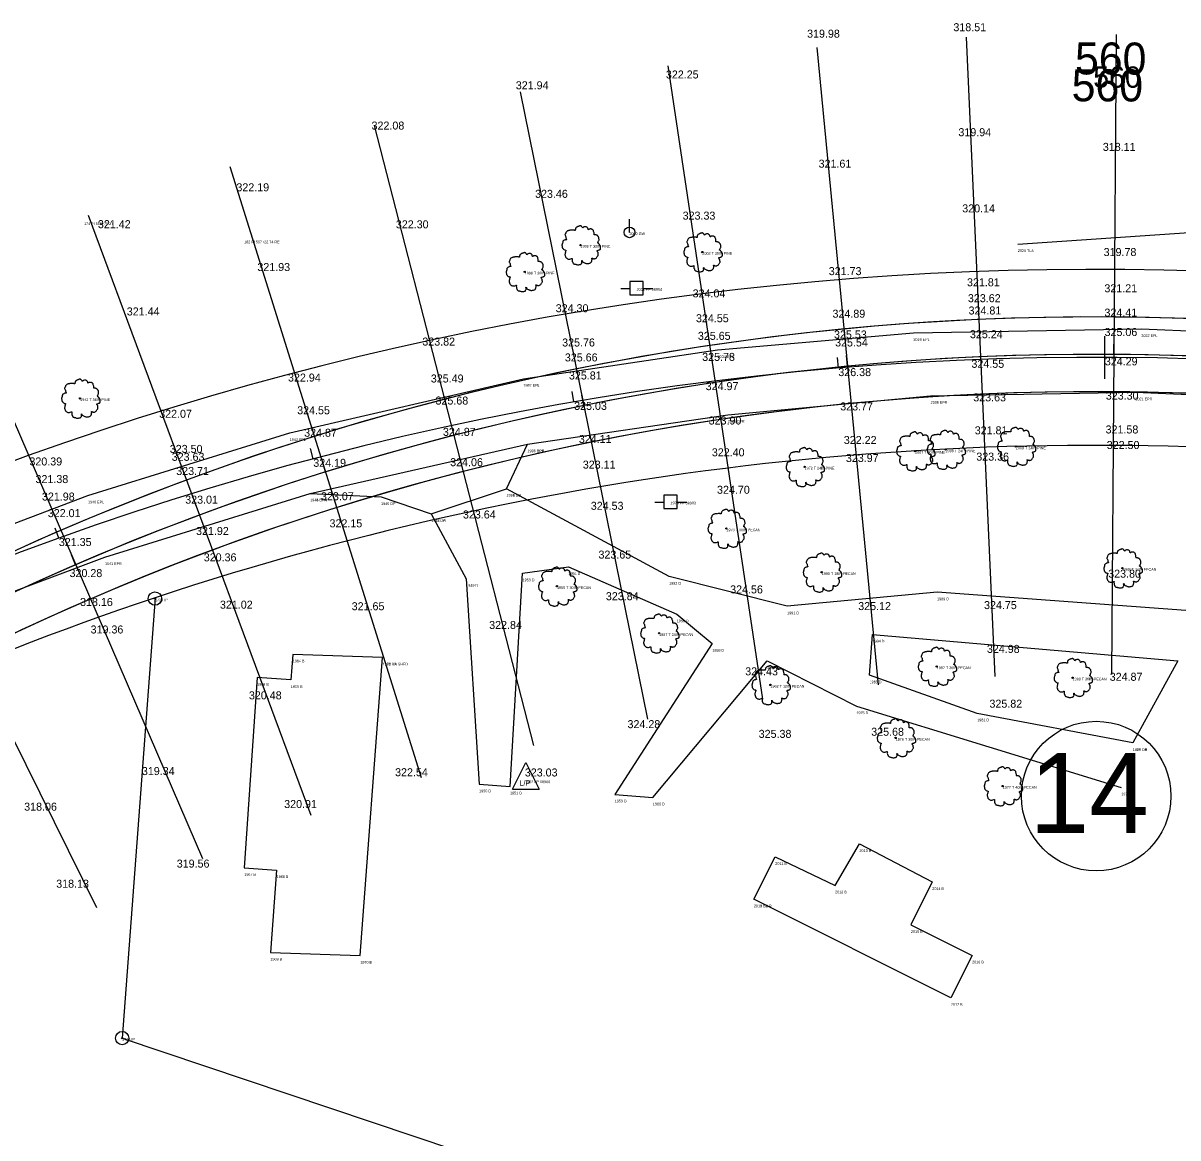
# Model space of a CAD drawing. Extents: x 49683 to 58852, y 49525 to 54803.
# Drawn here: x 56390.1 to 56823.1, y 53778.4 to 54196.4 of the extents above; entities that cross this region are included whole.
import ezdxf

# ---------------------------------------------------------------- set-up
doc = ezdxf.new("R2010")
doc.units = 0
for name, color, linetype in [('Level 1', 7, 'Continuous'), ('Level 11', 7, 'Continuous'), ('Level 12', 7, 'Continuous'), ('Level 13', 7, 'Continuous'), ('Level 19', 7, 'Continuous'), ('Level 20', 7, 'Continuous'), ('Level 21', 7, 'Continuous'), ('Level 25', 7, 'Continuous'), ('Level 29', 7, 'Continuous'), ('Level 3', 7, 'Continuous'), ('Level 32', 7, 'Continuous'), ('Level 50', 7, 'Continuous'), ('Level 51', 7, 'Continuous'), ('Level 53', 7, 'Continuous'), ('Level 58', 7, 'Continuous'), ('Level 59', 7, 'Continuous'), ('Level 61', 7, 'Continuous'), ('Level 62', 7, 'Continuous'), ('Level 63', 7, 'Continuous'), ('Level 8', 7, 'Continuous'), ('Level 9', 7, 'Continuous')]:
    doc.layers.add(name, color=color, linetype=linetype)

# ---------------------------------------------------------------- blocks, each defined once
blk = doc.blocks.new('IP')
at = {"layer": 'Level 12'}
for radius in [2.5, 0.25]:
    blk.add_circle((0, 0), radius, dxfattribs=at)
blk = doc.blocks.new('T1')
at = {"layer": 'Level 11'}
for centre, radius in [((0, 0), 0.25), ((-0.01, -0.02), 0.0001)]:
    blk.add_circle(centre, radius, dxfattribs=at)
for points in [[(0.13, 7.17), (-0.17, 7.19), (-0.49, 7.09), (-0.74, 6.99), (-0.97, 6.92), (-1.19, 6.82), (-1.49, 6.64), (-1.72, 6.44), (-1.84, 6.19), (-1.89, 5.97), (-1.94, 5.69), (-1.94, 5.52), (-2.07, 5.49), (-2.22, 5.52), (-2.47, 5.59), (-2.72, 5.59), (-2.97, 5.59), (-3.32, 5.57), (-3.67, 5.57), (-3.94, 5.52), (-4.27, 5.47), (-4.64, 5.34), (-4.99, 5.22), (-5.29, 4.97), (-5.54, 4.49), (-5.67, 4.14), (-5.82, 3.89), (-5.67, 3.44), (-5.49, 3.09), (-5.47, 2.89), (-5.39, 2.47), (-5.29, 2.24), (-5.17, 2.04), (-5.24, 2.02), (-5.62, 1.97), (-5.92, 1.87), (-6.34, 1.64), (-6.57, 1.42), (-6.67, 1.09), (-6.69, 0.75), (-6.79, 0.55), (-6.87, 0.27), (-6.89, 0.2), (-6.94, -0.13), (-6.84, -0.58), (-6.82, -0.93), (-6.69, -1.15), (-6.54, -1.33), (-6.37, -1.58), (-5.97, -1.8), (-5.64, -1.9), (-5.44, -1.93), (-5.62, -2.43), (-5.67, -2.78), (-5.79, -3.18), (-5.79, -3.25), (-5.84, -3.73), (-5.69, -4.05), (-5.62, -4.43), (-5.44, -4.65), (-5.17, -4.95), (-4.84, -5.18), (-4.34, -5.3), (-3.94, -5.28), (-3.37, -5.1), (-3.12, -5.03), (-3.14, -5.2), (-3.12, -5.58), (-3.12, -6), (-2.97, -6.33), (-2.87, -6.6), (-2.72, -6.85), (-2.39, -7.08), (-1.99, -7.15), (-1.57, -7.3), (-1.12, -7.38), (-0.62, -7.4), (-0.02, -7.25), (0.26, -7.13), (0.36, -6.95), (0.56, -6.58), (0.51, -6.35), (0.53, -5.75), (0.63, -5.93), (0.81, -6.28), (1.31, -6.58), (1.71, -6.75), (2.18, -6.9), (2.48, -6.98), (2.96, -6.9), (3.33, -6.83), (3.71, -6.7), (4.01, -6.43), (4.18, -6.15), (4.23, -5.88), (4.31, -5.5), (4.36, -5.33)], [(4.36, -5.33), (4.28, -5.15), (4.23, -4.9), (4.31, -4.93), (4.48, -4.98), (4.75, -5.1), (4.98, -5.18), (5.3, -5.15), (5.58, -5.05), (6.03, -4.78), (6.3, -4.3), (6.58, -3.9), (6.65, -3.58), (6.6, -3.35), (6.58, -2.85), (6.38, -2.6), (6.33, -2.48), (6.23, -2.08), (6.3, -2.03), (6.58, -1.98), (6.95, -1.85), (7.23, -1.73), (7.45, -1.55), (7.53, -1.33), (7.5, -0.93), (7.55, -0.53), (7.48, -0.38), (7.38, -0.23), (7.3, -0.03), (7.15, 0.12), (7.05, 0.27), (6.95, 0.37), (6.83, 0.52), (6.65, 0.65), (6.5, 0.7), (6.45, 0.85), (6.6, 1.04), (6.65, 1.14), (6.68, 1.37), (6.9, 1.72), (6.95, 2.12), (6.9, 2.54), (6.85, 2.82), (6.7, 3.09), (6.5, 3.34), (6.38, 3.52), (6.2, 3.64), (5.88, 3.77), (5.63, 3.82), (5.28, 3.82), (5.08, 3.87), (5.1, 3.92), (5.1, 4.07), (5.1, 4.34), (5.03, 4.79), (4.88, 5.29), (4.88, 5.32), (4.78, 5.57), (4.56, 5.77), (4.38, 5.87), (4.18, 5.99), (3.93, 6.02), (3.63, 6.02), (3.36, 5.97), (3.16, 5.87), (2.98, 5.74), (2.91, 5.89), (2.81, 6.19), (2.76, 6.34), (2.61, 6.52), (2.38, 6.72), (1.93, 6.84), (1.31, 6.77), (1.01, 6.57), (0.86, 6.39), (0.81, 6.52), (0.61, 6.72), (0.51, 6.89), (0.33, 7.02), (0.18, 7.12), (0.08, 7.17)]]:
    blk.add_spline(points, degree=3, dxfattribs=at)
blk = doc.blocks.new('LP')
at = {"layer": 'Level 9'}
for p, q in [((-4.79, -3.23), (0.21, 6.77)), ((0.21, 6.77), (5.21, -3.23)), ((-4.79, -3.23), (5.21, -3.23))]:
    blk.add_line(p, q, dxfattribs=at)
blk.add_text('L/P', height=2, dxfattribs=at).set_placement((-2.19, -1.95))
blk = doc.blocks.new('PP')
at = {"layer": 'Level 9'}
for p, q in [((2.53, 2.45), (-2.47, 2.45)), ((-2.47, 2.45), (-2.47, -2.55)), ((2.53, -2.55), (2.53, 2.45)), ((-5.91, -0.11), (-2.44, -0.11)), ((-2.47, -2.55), (2.53, -2.55)), ((2.45, -0.11), (6.09, -0.11))]:
    blk.add_line(p, q, dxfattribs=at)
blk = doc.blocks.new('GW')
at = {"layer": 'Level 9'}
blk.add_line((0, 0), (0, 5), dxfattribs=at)
blk.add_circle((0, 0), 2, dxfattribs=at)

msp = doc.modelspace()

# ---------------------------------------------------------------- linework, layer by layer
at = {"layer": 'Level 1'}
for p, q in [((56795.65, 54071.04), (56795.68, 54079.04)), ((56695.76, 54067.02), (56695.43, 54071.01)), ((56795.62, 54063.04), (56795.65, 54071.04)), ((56596.61, 54054.31), (56595.92, 54058.26)), ((56498.93, 54033.01), (56497.91, 54036.88)), ((56403.49, 54003.28), (56402.13, 54007.04))]:
    msp.add_line(p, q, dxfattribs=at)
at = {"layer": 'Level 11'}
msp.add_line((56763.02, 54113.51), (56919.7, 54124.18), dxfattribs=at)
at = {"layer": 'Level 12'}
for p, q in [((56439.6, 53980.87), (56427.28, 53815.81)), ((56427.28, 53815.81), (56690.99, 53727.29))]:
    msp.add_line(p, q, dxfattribs=at)
at = {"layer": 'Level 13'}
for radius, start, end in [(1178.92, 86.60044, 131.63335), (1112.92, 83.49442, 108.44495), (1112.92, 108.44495, 131.63335)]:
    msp.add_arc((56791.72, 52925.13), radius, start, end, dxfattribs=at)
at = {"layer": 'Level 19'}
for p, q in [((56799.06, 54072.17), (56799.12, 54080.17)), ((56699.21, 54067.73), (56698.82, 54071.71)), ((56799.06, 54072.17), (56799, 54064.17)), ((56600.34, 54052.98), (56599.55, 54056.9)), ((56503.54, 54028.08), (56502.34, 54031.9)), ((56409.83, 53993.31), (56408.24, 53996.98))]:
    msp.add_line(p, q, dxfattribs=at)
msp.add_arc((56791.96, 53107.19), 965, 83.49443, 131.63337, dxfattribs=at)
at = {"layer": 'Level 20'}
for radius, start in [(979, 83.49447), (951, 83.49446)]:
    msp.add_arc((56791.96, 53107.19), radius, start, 131.63337, dxfattribs=at)
at = {"layer": 'Level 25'}
msp.add_circle((56792.42, 53906.55), 28.04, dxfattribs=at)
at = {"layer": 'Level 29'}
for p, q in [((56795.65, 54071.04), (56795.68, 54079.04)), ((56695.76, 54067.02), (56695.43, 54071.01)), ((56596.61, 54054.31), (56595.93, 54058.26)), ((56498.93, 54033.01), (56497.91, 54036.88)), ((56403.49, 54003.28), (56402.14, 54007.04))]:
    msp.add_line(p, q, dxfattribs=at)
msp.add_arc((56791.72, 52925.13), 1145.92, 83.49443, 131.63333, dxfattribs=at)
at = {"layer": 'Level 3'}
for p, q in [((56723.9, 54080.24), (56809.36, 54081.7)), ((56809.36, 54081.7), (56872.82, 54079.01)), ((56650.48, 54073.81), (56723.9, 54080.24)), ((56577.69, 54063.01), (56650.48, 54073.81)), ((56490.09, 54042.73), (56577.69, 54063.01)), ((56654.29, 54049.54), (56730.36, 54056.66)), ((56730.36, 54056.66), (56807.13, 54057.96)), ((56807.13, 54057.96), (56873.04, 54055.26)), ((56579.24, 54038.47), (56654.29, 54049.54)), ((56414.45, 54019.29), (56490.09, 54042.73)), ((56497.78, 54020.06), (56579.24, 54038.47)), ((56340.54, 53991.29), (56414.45, 54019.29)), ((56420.81, 53996.17), (56497.78, 54020.06)), ((56350.09, 53969.49), (56420.81, 53996.17))]:
    msp.add_line(p, q, dxfattribs=at)
at = {"layer": 'Level 50'}
for p, q in [((56743.74, 54191.12), (56754.41, 53951.36)), ((56799.95, 54192.16), (56798.18, 53952.17)), ((56687.67, 54187.17), (56710.74, 53948.28)), ((56631.88, 54180.32), (56667.29, 53942.95)), ((56576.52, 54170.59), (56624.17, 53935.37)), ((56521.73, 54158), (56581.51, 53925.57)), ((56467.67, 54142.6), (56539.4, 53913.57)), ((56414.48, 54124.41), (56497.98, 53899.41)), ((56362.31, 54103.5), (56457.35, 53883.12)), ((56311.29, 54079.91), (56417.61, 53864.75))]:
    msp.add_line(p, q, dxfattribs=at)
at = {"layer": 'Level 63'}
for radius in [979, 965, 965, 951]:
    msp.add_arc((56791.96, 53107.19), radius, 87.29416, 127.83345, dxfattribs=at)
at = {"layer": 'Level 8'}
for p, q in [((56571.37, 54021.8), (56579.24, 54038.47)), ((56543.14, 54012.37), (56571.37, 54021.8)), ((56632.32, 53988.82), (56571.37, 54021.8)), ((56497.78, 54020.06), (56524.35, 54018.72)), ((56524.35, 54018.72), (56543.14, 54012.37)), ((56543.14, 54012.37), (56556.26, 53988.01)), ((56577.39, 53990.09), (56594.57, 53992.46)), ((56594.57, 53992.46), (56635.17, 53974.75)), ((56556.26, 53988.01), (56561.1, 53910.97)), ((56572.68, 53910.19), (56577.39, 53990.09)), ((56676.58, 53977.7), (56632.32, 53988.82)), ((56732.77, 53982.97), (56676.58, 53977.7)), ((56836.65, 53975.32), (56732.77, 53982.97)), ((56635.17, 53974.75), (56648.5, 53963.72)), ((56707.47, 53951.83), (56708.57, 53967.14)), ((56708.57, 53967.14), (56823.01, 53957.2)), ((56648.5, 53963.72), (56611.93, 53907.19)), ((56491.23, 53959.69), (56490.52, 53950.11)), ((56524.93, 53958.52), (56491.23, 53959.69)), ((56516.55, 53846.72), (56524.93, 53958.52)), ((56626.22, 53906.07), (56669.07, 53957.29)), ((56669.07, 53957.29), (56702.53, 53940.27)), ((56823.01, 53957.2), (56806.15, 53926.5)), ((56747.83, 53937.57), (56707.47, 53951.83)), ((56477.85, 53950.96), (56473.05, 53879.64)), ((56490.52, 53950.11), (56477.85, 53950.96)), ((56702.53, 53940.27), (56801.83, 53909.79)), ((56806.15, 53926.5), (56747.83, 53937.57)), ((56561.1, 53910.97), (56572.68, 53910.19)), ((56611.93, 53907.19), (56626.22, 53906.07)), ((56694.51, 53873.08), (56703.69, 53888.59)), ((56703.69, 53888.59), (56730.98, 53874.36)), ((56664.09, 53867.85), (56672.11, 53883.72)), ((56672.11, 53883.72), (56694.51, 53873.08)), ((56473.05, 53879.64), (56485.18, 53878.82)), ((56485.18, 53878.82), (56482.86, 53847.89)), ((56730.98, 53874.36), (56722.98, 53858.23)), ((56737.97, 53830.92), (56664.09, 53867.85)), ((56722.98, 53858.23), (56745.89, 53846.83)), ((56482.86, 53847.89), (56516.55, 53846.72)), ((56745.89, 53846.83), (56737.97, 53830.92))]:
    msp.add_line(p, q, dxfattribs=at)

# ---------------------------------------------------------------- block references
at = {"layer": 'Level 11'}
for p in [(56599.09, 54113.16), (56644.76, 54110.52), (56578.18, 54103.12), (56411.51, 54055.66), (56724.52, 54035.91), (56735.97, 54036.49), (56762.31, 54037.59), (56683.1, 54030), (56653.82, 54006.87), (56802.24, 53992.01), (56689.55, 53990.45), (56590.28, 53985.2), (56628.59, 53967.6), (56732.63, 53955.14), (56783.57, 53950.92), (56670.3, 53948.23), (56717.25, 53928.33), (56757.4, 53910.32)]:
    msp.add_blockref('T1', p, dxfattribs=at)
at = {"layer": 'Level 12'}
for p in [(56439.58, 53980.62), (56427.28, 53815.81)]:
    msp.add_blockref('IP', p, dxfattribs=at)
at = {"layer": 'Level 9'}
for name, p in [('GW', (56617.45, 54117.92)), ('PP', (56620.12, 54097.01)), ('PP', (56632.83, 54016.9)), ('LP', (56578.36, 53912.4))]:
    msp.add_blockref(name, p, dxfattribs=at)

# ---------------------------------------------------------------- texts
at = {"layer": 'Level 19'}
msp.add_text('560', height=8, rotation=359.5783, dxfattribs=at).set_placement((56791.28, 54172.23))
at = {"layer": 'Level 21'}
for rotation, p in [(359.8036, (56784.46, 54177.15)), (359.8035, (56783.21, 54167.08))]:
    msp.add_text('560', height=12, rotation=rotation, dxfattribs=at).set_placement(p)
at = {"layer": 'Level 25'}
msp.add_text('14', height=30, dxfattribs=at).set_placement((56767.49, 53892.67))
at = {"layer": 'Level 32'}
for s, p in [('319.98', (56684.05, 54190.91)), ('318.51', (56738.89, 54193.33)), ('322.25', (56631.11, 54175.61)), ('321.94', (56574.84, 54171.56)), ('322.08', (56520.77, 54156.45)), ('319.94', (56740.77, 54153.97)), ('318.11', (56794.92, 54148.46)), ('321.61', (56688.36, 54142.16)), ('322.19', (56470.1, 54133.32)), ('323.46', (56582.07, 54130.86)), ('323.33', (56637.39, 54122.69)), ('320.14', (56742.21, 54125.4)), ('321.42', (56418.18, 54119.48)), ('322.30', (56529.88, 54119.42)), ('319.78', (56795.22, 54109.03)), ('321.93', (56477.96, 54103.41)), ('321.73', (56692.17, 54101.88)), ('321.81', (56743.99, 54097.7)), ('321.21', (56795.5, 54095.44)), ('324.04', (56641.14, 54093.53)), ('323.62', (56744.33, 54091.73)), ('321.44', (56429, 54086.76)), ('324.30', (56589.81, 54087.97)), ('324.81', (56744.58, 54087.12)), ('324.55', (56642.39, 54084.22)), ('324.89', (56693.57, 54085.92)), ('324.41', (56795.52, 54086.33)), ('325.53', (56694.13, 54078.12)), ('325.24', (56745.09, 54078.23)), ('325.06', (56795.56, 54079.04)), ('323.82', (56539.8, 54075.46)), ('325.76', (56592.22, 54075.12)), ('325.65', (56643.1, 54077.61)), ('325.54', (56694.54, 54075.14)), ('325.66', (56593.23, 54069.52)), ('325.78', (56644.72, 54069.72)), ('324.55', (56745.65, 54067.13)), ('324.29', (56795.66, 54068.04)), ('322.94', (56489.45, 54061.97)), ('325.49', (56542.98, 54061.62)), ('325.81', (56594.76, 54062.75)), ('326.38', (56695.75, 54064.02)), ('324.97', (56646.03, 54058.75)), ('325.68', (56544.74, 54053.35)), ('323.63', (56746.34, 54054.55)), ('323.30', (56796.03, 54055.2)), ('322.07', (56441.15, 54048.39)), ('324.55', (56492.89, 54049.71)), ('325.03', (56596.72, 54051.35)), ('323.77', (56696.46, 54051.15)), ('323.90', (56647.15, 54045.87)), ('324.87', (56495.5, 54041.28)), ('324.87', (56547.53, 54041.61)), ('321.81', (56746.89, 54042.18)), ('321.58', (56795.95, 54042.51)), ('323.50', (56445.13, 54035.22)), ('324.11', (56598.47, 54038.95)), ('322.22', (56697.81, 54038.56)), ('322.50', (56796.38, 54036.69)), ('320.39', (56392.5, 54030.52)), ('323.63', (56445.85, 54032.26)), ('322.40', (56648.34, 54033.94)), ('323.97', (56698.59, 54031.81)), ('323.36', (56747.48, 54032.33)), ('323.71', (56447.55, 54026.94)), ('324.19', (56498.93, 54030.01)), ('324.06', (56550.24, 54030.24)), ('323.11', (56599.96, 54029.33)), ('321.38', (56394.79, 54023.91)), ('321.98', (56397.2, 54017.36)), ('323.07', (56501.82, 54017.48)), ('324.70', (56650.28, 54019.9)), ('323.01', (56450.91, 54016.19)), ('324.53', (56602.95, 54013.89)), ('322.01', (56399.39, 54011.14)), ('323.64', (56555.04, 54010.63)), ('321.92', (56454.97, 54004.45)), ('322.15', (56505.01, 54007.31)), ('321.35', (56403.53, 54000.3)), ('320.36', (56457.86, 53994.57)), ('323.65', (56605.84, 53995.6)), ('320.28', (56407.55, 53988.66)), ('323.80', (56796.93, 53988.44)), ('323.84', (56608.61, 53979.99)), ('324.56', (56655.2, 53982.54)), ('318.16', (56411.49, 53977.82)), ('321.02', (56463.93, 53976.82)), ('321.65', (56513.32, 53976.23)), ('325.12', (56703.21, 53976.29)), ('324.75', (56750.38, 53976.66)), ('319.36', (56415.44, 53967.52)), ('322.84', (56564.86, 53969.21)), ('324.98', (56751.46, 53960.24)), ('324.43', (56660.84, 53951.82)), ('324.87', (56797.49, 53949.78)), ('320.48', (56474.79, 53942.83)), ('325.82', (56752.41, 53939.69)), ('324.28', (56616.73, 53932.02)), ('325.38', (56665.9, 53928.38)), ('325.68', (56708.09, 53929.17)), ('319.34', (56434.67, 53914.43)), ('322.54', (56529.59, 53914)), ('323.03', (56578.22, 53913.91)), ('318.06', (56390.54, 53901.08)), ('320.91', (56488.01, 53902.07)), ('319.56', (56447.74, 53879.74)), ('318.13', (56402.55, 53872.2))]:
    msp.add_text(s, height=3, dxfattribs=at).set_placement(p)
at = {"layer": 'Level 51'}
for s, p in [('174 PI 556+75.27 ', (56412.99, 54120.66)), ('182 PI 557+22.74 RE ', (56473.02, 54113.82))]:
    msp.add_text(s, height=1, dxfattribs=at).set_placement(p)
at = {"layer": 'Level 53'}
for s, p in [('2019 EPL ', (56723.9, 54077.24)), ('2022 EPL ', (56809.36, 54078.7)), ('2004 EPL ', (56650.48, 54070.81)), ('1997 EPL ', (56577.69, 54060.01)), ('2021 EPR ', (56807.13, 54054.96)), ('2006 EPR ', (56730.36, 54053.66)), ('2005 EPR ', (56654.29, 54046.54)), ('1943 EPL ', (56490.09, 54039.73)), ('1996 EPR ', (56579.24, 54035.47)), ('1940 EPL ', (56414.45, 54016.29)), ('1944 EPR ', (56497.78, 54017.06)), ('1941 EPR ', (56420.81, 53993.17))]:
    msp.add_text(s, height=1, dxfattribs=at).set_placement(p)
at = {"layer": 'Level 58'}
for s, p in [('1995 DPB ', (56579.24, 54035.47)), ('1945 DPA ', (56497.78, 54017.06)), ('1946 DP ', (56524.35, 54015.72)), ('1993 DB ', (56571.37, 54018.8)), ('1994 DP ', (56571.37, 54018.8)), ('1948 DA ', (56543.14, 54009.37)), ('1947 DP ', (56543.14, 54009.37)), ('1954 D ', (56594.57, 53989.46)), ('1949 D ', (56556.26, 53985.01)), ('1953 D ', (56577.39, 53987.09)), ('1992 D ', (56632.32, 53985.82)), ('1989 D ', (56732.77, 53979.97)), ('1991 D ', (56676.58, 53974.7)), ('1956 D ', (56635.17, 53971.75)), ('1984 D ', (56708.57, 53964.14)), ('1958 D ', (56648.5, 53960.72)), ('1964 B ', (56491.23, 53956.69)), ('1963 BA SHED ', (56524.93, 53955.52)), ('1971 BB ', (56524.93, 53955.52)), ('1961 D ', (56669.07, 53954.29)), ('1966 B ', (56477.85, 53947.96)), ('1965 B ', (56490.52, 53947.11)), ('1983 D ', (56707.47, 53948.83)), ('1975 D ', (56702.53, 53937.27)), ('1981 D ', (56747.83, 53934.57)), ('1979 DA ', (56806.15, 53923.5)), ('1986 DB ', (56806.15, 53923.5)), ('1950 D ', (56561.1, 53907.97)), ('1951 D ', (56572.68, 53907.19)), ('1959 D ', (56611.93, 53904.19)), ('1960 D ', (56626.22, 53903.07)), ('1978 DB ', (56801.83, 53906.79)), ('2013 B ', (56703.69, 53885.59)), ('1967 B ', (56473.05, 53876.64)), ('2011 B ', (56672.11, 53880.72)), ('1968 B ', (56485.18, 53875.82)), ('2012 B ', (56694.51, 53870.08)), ('2014 B ', (56730.98, 53871.36)), ('2010 BA R ', (56664.09, 53864.85)), ('2018 BB ', (56664.09, 53864.85)), ('2015 B ', (56722.98, 53855.23)), ('1969 B ', (56482.86, 53844.89)), ('1970 B ', (56516.55, 53843.72)), ('2016 B ', (56745.89, 53843.83)), ('2017 B ', (56737.97, 53827.92))]:
    msp.add_text(s, height=1, dxfattribs=at).set_placement(p)
at = {"layer": 'Level 59'}
for s, p in [('2000 GW ', (56617.45, 54116.92)), ('2001 PP 08904 ', (56620.12, 54096.01)), ('1974 PP 08903 ', (56632.83, 54015.9)), ('1952 LP 08906 ', (56578.36, 53911.4))]:
    msp.add_text(s, height=1, dxfattribs=at).set_placement(p)
at = {"layer": 'Level 61'}
for s, p in [('1999 T 30IN PINE ', (56599.09, 54112.16)), ('2020 TLA ', (56763.02, 54110.51)), ('2003 T 30IN PINE ', (56644.76, 54109.52)), ('1998 T 30IN PINE ', (56578.18, 54102.12)), ('1942 T 36IN PINE ', (56411.51, 54054.66)), ('2007 T 30IN PINE ', (56724.52, 54034.91)), ('2008 T 24IN PINE ', (56735.97, 54035.49)), ('2009 T 24IN PINE ', (56762.31, 54036.59)), ('1972 T 24IN PINE ', (56683.1, 54029)), ('1973 T 30IN PECAN ', (56653.82, 54005.87)), ('1990 T 18IN PECAN ', (56689.55, 53989.45)), ('1988 T 24IN PECAN ', (56802.24, 53991.01)), ('1955 T 30IN PECAN ', (56590.28, 53984.2)), ('1957 T 24IN PECAN ', (56628.59, 53966.6)), ('1982 T 36IN PECAN ', (56732.63, 53954.14)), ('1962 T 12IN PECAN ', (56670.3, 53947.23)), ('1980 T 36IN PECAN ', (56783.57, 53949.92)), ('1976 T 30IN PECAN ', (56717.25, 53927.33)), ('1977 T 40IN PECAN ', (56757.4, 53909.32))]:
    msp.add_text(s, height=1, dxfattribs=at).set_placement(p)
at = {"layer": 'Level 62'}
for s, p in [('1724 IP ', (56439.58, 53979.62)), ('1723 IP ', (56427.28, 53814.81))]:
    msp.add_text(s, height=1, dxfattribs=at).set_placement(p)

doc.saveas('drawing.dxf')
